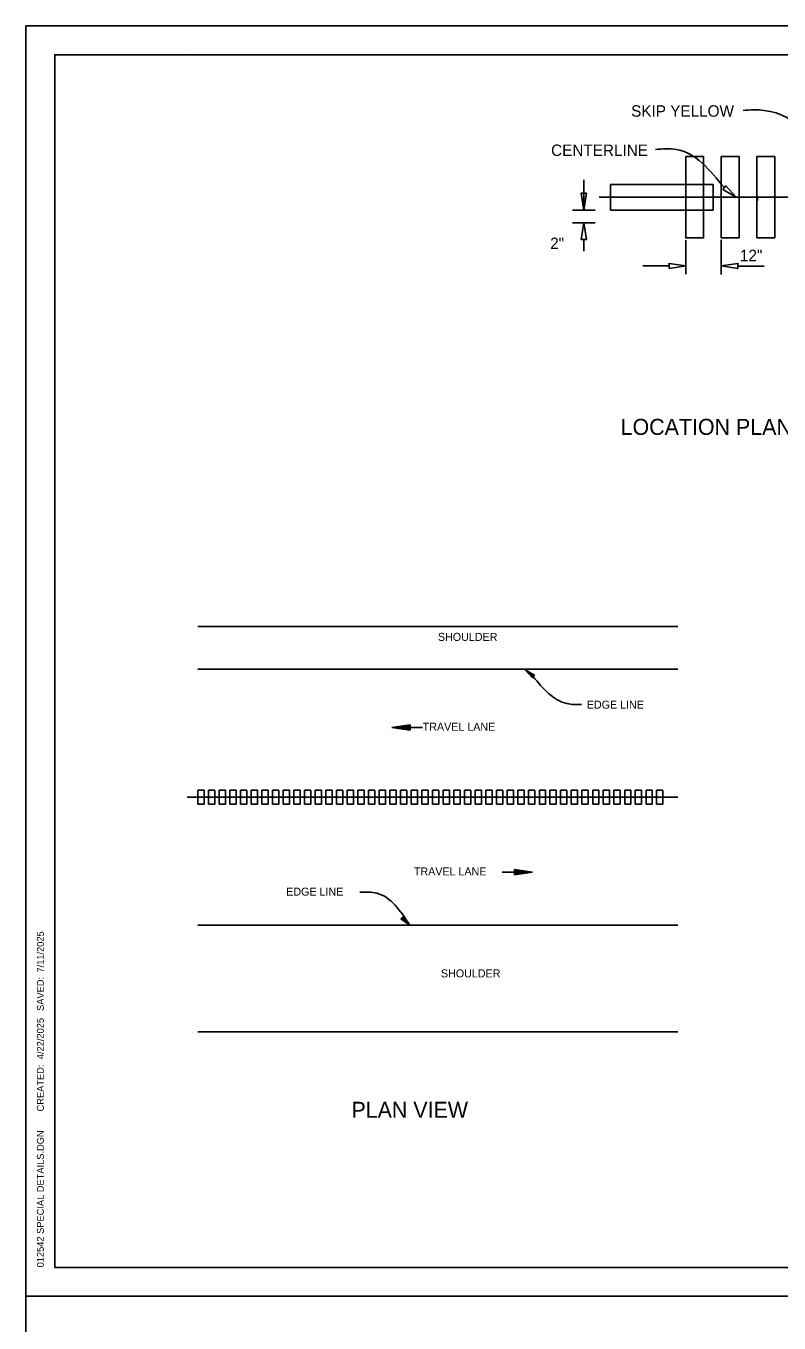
# Model space of a CAD drawing. Extents: x 1371343 to 1373043, y 378740 to 382040.
# Drawn here: x 1371343 to 1371995, y 380917 to 382040 of the extents above; entities that cross this region are included whole.
import ezdxf

# ---------------------------------------------------------------- set-up
doc = ezdxf.new("R2010")
doc.units = 0
for name, color, linetype in [('Default', 7, 'Continuous'), ('E_Existing ROW', 7, 'Continuous'), ('R_Alt Surface Annot', 7, 'Continuous'), ('R_Border Notes', 7, 'Continuous')]:
    doc.layers.add(name, color=color, linetype=linetype)

msp = doc.modelspace()

# ---------------------------------------------------------------- linework, layer by layer
at = {"layer": 'Default'}
for p, q in [((1371826, 381881.1), (1371826, 381907.2)), ((1371839.4, 381892.1), (1372448.3, 381892.1)), ((1371816.2, 381881.1), (1371835.9, 381881.1)), ((1371816.2, 381870.1), (1371835.9, 381870.1)), ((1371826, 381845.4), (1371826, 381855.7)), ((1371914.3, 381825.5), (1371914.3, 381855.1)), ((1371945.1, 381825.4), (1371945.1, 381855.2)), ((1371899.8, 381832.7), (1371877.2, 381832.7)), ((1371982.2, 381832.6), (1371959.5, 381832.6))]:
    msp.add_line(p, q, dxfattribs=at)
for points in [[(1371914.3, 381927.4), (1371914.3, 381856.9), (1371929.7, 381856.9), (1371929.7, 381927.4)], [(1371945.1, 381927.4), (1371945.1, 381856.9), (1371960.5, 381856.9), (1371960.5, 381927.4)], [(1371975.9, 381927.4), (1371975.9, 381856.9), (1371991.4, 381856.9), (1371991.4, 381927.4)]]:
    msp.add_lwpolyline(points, close=True, dxfattribs=at)
for points in [[(1371964, 381967.4), (1371982.2, 381967.4), (1372052.5, 381911.4)], [(1371888.1, 381933.6), (1371906, 381933.6), (1371947.7, 381900.4)]]:
    msp.add_spline(points, degree=3, dxfattribs=at)
at = {"layer": 'E_Existing ROW'}
for p, q in [((1371484, 382019.1), (1371484, 382019.1)), ((1371484, 382019.1), (1371484, 382019.1)), ((1371484, 380919.1), (1371484, 380919.1)), ((1371484, 380919.1), (1371484, 380919.1))]:
    msp.add_line(p, q, dxfattribs=at)
for points in [[(1371342.9, 380940.5), (1373042.9, 380940.5), (1373042.9, 382040.5), (1371342.9, 382040.5)], [(1371367.9, 380965.5), (1373017.9, 380965.5), (1373017.9, 382015.5), (1371367.9, 382015.5)], [(1371342.9, 379840.5), (1373042.9, 379840.5), (1373042.9, 380940.5), (1371342.9, 380940.5)]]:
    msp.add_lwpolyline(points, close=True, dxfattribs=at)
at = {"layer": 'R_Border Notes'}
for p, q in [((1371849, 381903.2), (1371849, 381881.1)), ((1371849, 381903.2), (1371937.9, 381903.2)), ((1371937.9, 381903.2), (1371937.9, 381881.1)), ((1371976.3, 381892.1), (1371976.3, 381889.3)), ((1371849, 381881.1), (1371937.9, 381881.1)), ((1371491.8, 381520.5), (1371907.4, 381520.5)), ((1371491.8, 381483.6), (1371698.6, 381483.6)), ((1371907.4, 381483.6), (1371698.6, 381483.6)), ((1371781.5, 381476), (1371775.1, 381482.9)), ((1371783.2, 381478.2), (1371775.1, 381482.9)), ((1371781.6, 381476.2), (1371776.3, 381481.9)), ((1371783.1, 381478), (1371776.3, 381481.9)), ((1371782.9, 381477.8), (1371777.6, 381480.9)), ((1371781.8, 381476.4), (1371777.6, 381480.9)), ((1371781.9, 381476.6), (1371778.8, 381480)), ((1371782.8, 381477.6), (1371778.8, 381480)), ((1371782.6, 381477.4), (1371780, 381479)), ((1371782.1, 381476.7), (1371780, 381479)), ((1371782.5, 381477.3), (1371781.2, 381478)), ((1371782.2, 381476.9), (1371781.2, 381478)), ((1371781.5, 381476), (1371783.2, 381478.2)), ((1371675.5, 381435.2), (1371659.9, 381432.9)), ((1371686.4, 381432.9), (1371659.9, 381432.9)), ((1371675.5, 381430.6), (1371659.9, 381432.9)), ((1371675.5, 381434.8), (1371662.5, 381432.9)), ((1371675.5, 381431), (1371662.5, 381432.9)), ((1371675.5, 381434.5), (1371665.2, 381432.9)), ((1371675.5, 381431.4), (1371665.2, 381432.9)), ((1371675.5, 381434.1), (1371667.7, 381432.9)), ((1371675.5, 381431.7), (1371667.7, 381432.9)), ((1371675.5, 381433.6), (1371670.4, 381432.9)), ((1371675.5, 381432.1), (1371670.4, 381432.9)), ((1371675.5, 381433.3), (1371673, 381432.9)), ((1371675.5, 381432.5), (1371673, 381432.9)), ((1371675.5, 381435.2), (1371675.5, 381430.6)), ((1371497.2, 381378.8), (1371491.8, 381378.8)), ((1371491.8, 381378.8), (1371491.8, 381366.6)), ((1371497.2, 381378.8), (1371497.2, 381366.6)), ((1371506.4, 381378.8), (1371501, 381378.8)), ((1371501, 381378.8), (1371501, 381366.6)), ((1371506.4, 381378.8), (1371506.4, 381366.6)), ((1371515.7, 381378.8), (1371510.3, 381378.8)), ((1371510.3, 381378.8), (1371510.3, 381366.6)), ((1371515.7, 381378.8), (1371515.7, 381366.6)), ((1371524.9, 381378.8), (1371519.5, 381378.8)), ((1371519.5, 381378.8), (1371519.5, 381366.6)), ((1371524.9, 381378.8), (1371524.9, 381366.6)), ((1371534.1, 381378.8), (1371528.7, 381378.8)), ((1371528.7, 381378.8), (1371528.7, 381366.6)), ((1371534.1, 381378.8), (1371534.1, 381366.6)), ((1371543.4, 381378.8), (1371538, 381378.8)), ((1371538, 381378.8), (1371538, 381366.6)), ((1371543.4, 381378.8), (1371543.4, 381366.6)), ((1371552.6, 381378.8), (1371547.2, 381378.8)), ((1371547.2, 381378.8), (1371547.2, 381366.6)), ((1371552.6, 381378.8), (1371552.6, 381366.6)), ((1371561.9, 381378.8), (1371556.5, 381378.8)), ((1371556.5, 381378.8), (1371556.5, 381366.6)), ((1371561.9, 381378.8), (1371561.9, 381366.6)), ((1371571.1, 381378.8), (1371565.7, 381378.8)), ((1371565.7, 381378.8), (1371565.7, 381366.6)), ((1371571.1, 381378.8), (1371571.1, 381366.6)), ((1371580.3, 381378.8), (1371574.9, 381378.8)), ((1371574.9, 381378.8), (1371574.9, 381366.6)), ((1371580.3, 381378.8), (1371580.3, 381366.6)), ((1371589.6, 381378.8), (1371584.2, 381378.8)), ((1371584.2, 381378.8), (1371584.2, 381366.6)), ((1371589.6, 381378.8), (1371589.6, 381366.6)), ((1371598.8, 381378.8), (1371593.4, 381378.8)), ((1371593.4, 381378.8), (1371593.4, 381366.6)), ((1371598.8, 381378.8), (1371598.8, 381366.6)), ((1371608.1, 381378.8), (1371602.7, 381378.8)), ((1371602.7, 381378.8), (1371602.7, 381366.6)), ((1371608.1, 381378.8), (1371608.1, 381366.6)), ((1371617.3, 381378.8), (1371611.9, 381378.8)), ((1371611.9, 381378.8), (1371611.9, 381366.6)), ((1371617.3, 381378.8), (1371617.3, 381366.6)), ((1371626.5, 381378.8), (1371621.1, 381378.8)), ((1371621.1, 381378.8), (1371621.1, 381366.6)), ((1371626.5, 381378.8), (1371626.5, 381366.6)), ((1371635.8, 381378.8), (1371630.4, 381378.8)), ((1371630.4, 381378.8), (1371630.4, 381366.6)), ((1371635.8, 381378.8), (1371635.8, 381366.6)), ((1371645, 381378.8), (1371639.6, 381378.8)), ((1371639.6, 381378.8), (1371639.6, 381366.6)), ((1371645, 381378.8), (1371645, 381366.6)), ((1371654.3, 381378.8), (1371648.9, 381378.8)), ((1371648.9, 381378.8), (1371648.9, 381366.6)), ((1371654.3, 381378.8), (1371654.3, 381366.6)), ((1371663.5, 381378.8), (1371658.1, 381378.8)), ((1371658.1, 381378.8), (1371658.1, 381366.6)), ((1371663.5, 381378.8), (1371663.5, 381366.6)), ((1371672.7, 381378.8), (1371667.3, 381378.8)), ((1371667.3, 381378.8), (1371667.3, 381366.6)), ((1371672.7, 381378.8), (1371672.7, 381366.6)), ((1371682, 381378.8), (1371676.6, 381378.8)), ((1371676.6, 381378.8), (1371676.6, 381366.6)), ((1371682, 381378.8), (1371682, 381366.6)), ((1371691.2, 381378.8), (1371685.8, 381378.8)), ((1371685.8, 381378.8), (1371685.8, 381366.6)), ((1371691.2, 381378.8), (1371691.2, 381366.6)), ((1371700.5, 381378.8), (1371695.1, 381378.8)), ((1371695.1, 381378.8), (1371695.1, 381366.6)), ((1371700.5, 381378.8), (1371700.5, 381366.6)), ((1371709.7, 381378.8), (1371704.3, 381378.8)), ((1371704.3, 381378.8), (1371704.3, 381366.6)), ((1371709.7, 381378.8), (1371709.7, 381366.6)), ((1371719, 381378.8), (1371713.5, 381378.8)), ((1371713.5, 381378.8), (1371713.5, 381366.6)), ((1371719, 381378.8), (1371719, 381366.6)), ((1371728.2, 381378.8), (1371722.8, 381378.8)), ((1371722.8, 381378.8), (1371722.8, 381366.6)), ((1371728.2, 381378.8), (1371728.2, 381366.6)), ((1371737.4, 381378.8), (1371732, 381378.8)), ((1371732, 381378.8), (1371732, 381366.6)), ((1371737.4, 381378.8), (1371737.4, 381366.6)), ((1371746.7, 381378.8), (1371741.3, 381378.8)), ((1371741.3, 381378.8), (1371741.3, 381366.6)), ((1371746.7, 381378.8), (1371746.7, 381366.6)), ((1371755.9, 381378.8), (1371750.5, 381378.8)), ((1371750.5, 381378.8), (1371750.5, 381366.6)), ((1371755.9, 381378.8), (1371755.9, 381366.6)), ((1371765.2, 381378.8), (1371759.7, 381378.8)), ((1371759.7, 381378.8), (1371759.7, 381366.6)), ((1371765.2, 381378.8), (1371765.2, 381366.6)), ((1371774.4, 381378.8), (1371769, 381378.8)), ((1371769, 381378.8), (1371769, 381366.6)), ((1371774.4, 381378.8), (1371774.4, 381366.6)), ((1371783.6, 381378.8), (1371778.2, 381378.8)), ((1371778.2, 381378.8), (1371778.2, 381366.6)), ((1371783.6, 381378.8), (1371783.6, 381366.6)), ((1371792.9, 381378.8), (1371787.5, 381378.8)), ((1371787.5, 381378.8), (1371787.5, 381366.6)), ((1371792.9, 381378.8), (1371792.9, 381366.6)), ((1371802.1, 381378.8), (1371796.7, 381378.8)), ((1371796.7, 381378.8), (1371796.7, 381366.6)), ((1371802.1, 381378.8), (1371802.1, 381366.6)), ((1371811.4, 381378.8), (1371805.9, 381378.8)), ((1371805.9, 381378.8), (1371805.9, 381366.6)), ((1371811.4, 381378.8), (1371811.4, 381366.6)), ((1371820.6, 381378.8), (1371815.2, 381378.8)), ((1371815.2, 381378.8), (1371815.2, 381366.6)), ((1371820.6, 381378.8), (1371820.6, 381366.6)), ((1371829.8, 381378.8), (1371824.4, 381378.8)), ((1371824.4, 381378.8), (1371824.4, 381366.6)), ((1371829.8, 381378.8), (1371829.8, 381366.6)), ((1371839.1, 381378.8), (1371833.7, 381378.8)), ((1371833.7, 381378.8), (1371833.7, 381366.6)), ((1371839.1, 381378.8), (1371839.1, 381366.6)), ((1371848.3, 381378.8), (1371842.9, 381378.8)), ((1371842.9, 381378.8), (1371842.9, 381366.6)), ((1371848.3, 381378.8), (1371848.3, 381366.6)), ((1371857.6, 381378.8), (1371852.1, 381378.8)), ((1371852.1, 381378.8), (1371852.1, 381366.6)), ((1371857.6, 381378.8), (1371857.6, 381366.6)), ((1371866.8, 381378.8), (1371861.4, 381378.8)), ((1371861.4, 381378.8), (1371861.4, 381366.6)), ((1371866.8, 381378.8), (1371866.8, 381366.6)), ((1371876, 381378.8), (1371870.6, 381378.8)), ((1371870.6, 381378.8), (1371870.6, 381366.6)), ((1371876, 381378.8), (1371876, 381366.6)), ((1371885.3, 381378.8), (1371879.9, 381378.8)), ((1371879.9, 381378.8), (1371879.9, 381366.6)), ((1371885.3, 381378.8), (1371885.3, 381366.6)), ((1371894.5, 381378.8), (1371889.1, 381378.8)), ((1371889.1, 381378.8), (1371889.1, 381366.6)), ((1371894.5, 381378.8), (1371894.5, 381366.6)), ((1371482.6, 381372.7), (1371907.4, 381372.7)), ((1371491.8, 381366.6), (1371497.2, 381366.6)), ((1371501, 381366.6), (1371506.4, 381366.6)), ((1371510.3, 381366.6), (1371515.7, 381366.6)), ((1371519.5, 381366.6), (1371524.9, 381366.6)), ((1371528.7, 381366.6), (1371534.1, 381366.6)), ((1371538, 381366.6), (1371543.4, 381366.6)), ((1371547.2, 381366.6), (1371552.6, 381366.6)), ((1371556.5, 381366.6), (1371561.9, 381366.6)), ((1371565.7, 381366.6), (1371571.1, 381366.6)), ((1371574.9, 381366.6), (1371580.3, 381366.6)), ((1371584.2, 381366.6), (1371589.6, 381366.6)), ((1371593.4, 381366.6), (1371598.8, 381366.6)), ((1371602.7, 381366.6), (1371608.1, 381366.6)), ((1371611.9, 381366.6), (1371617.3, 381366.6)), ((1371621.1, 381366.6), (1371626.5, 381366.6)), ((1371630.4, 381366.6), (1371635.8, 381366.6)), ((1371639.6, 381366.6), (1371645, 381366.6)), ((1371648.9, 381366.6), (1371654.3, 381366.6)), ((1371658.1, 381366.6), (1371663.5, 381366.6)), ((1371667.3, 381366.6), (1371672.7, 381366.6)), ((1371676.6, 381366.6), (1371682, 381366.6)), ((1371685.8, 381366.6), (1371691.2, 381366.6)), ((1371695.1, 381366.6), (1371700.5, 381366.6)), ((1371704.3, 381366.6), (1371709.7, 381366.6)), ((1371713.5, 381366.6), (1371719, 381366.6)), ((1371722.8, 381366.6), (1371728.2, 381366.6)), ((1371732, 381366.6), (1371737.4, 381366.6)), ((1371741.3, 381366.6), (1371746.7, 381366.6)), ((1371750.5, 381366.6), (1371755.9, 381366.6)), ((1371759.7, 381366.6), (1371765.2, 381366.6)), ((1371769, 381366.6), (1371774.4, 381366.6)), ((1371778.2, 381366.6), (1371783.6, 381366.6)), ((1371787.5, 381366.6), (1371792.9, 381366.6)), ((1371796.7, 381366.6), (1371802.1, 381366.6)), ((1371805.9, 381366.6), (1371811.4, 381366.6)), ((1371815.2, 381366.6), (1371820.6, 381366.6)), ((1371824.4, 381366.6), (1371829.8, 381366.6)), ((1371833.7, 381366.6), (1371839.1, 381366.6)), ((1371842.9, 381366.6), (1371848.3, 381366.6)), ((1371852.1, 381366.6), (1371857.6, 381366.6)), ((1371861.4, 381366.6), (1371866.8, 381366.6)), ((1371870.6, 381366.6), (1371876, 381366.6)), ((1371879.9, 381366.6), (1371885.3, 381366.6)), ((1371889.1, 381366.6), (1371894.5, 381366.6)), ((1371755.2, 381307.8), (1371781.6, 381307.8)), ((1371766.1, 381310.1), (1371781.6, 381307.8)), ((1371766.1, 381305.5), (1371766.1, 381310.1)), ((1371766.1, 381309.7), (1371779, 381307.8)), ((1371766.1, 381309.3), (1371776.4, 381307.8)), ((1371766.1, 381308.9), (1371773.8, 381307.8)), ((1371766.1, 381308.6), (1371771.1, 381307.8)), ((1371766.1, 381308.2), (1371768.5, 381307.8)), ((1371766.1, 381305.5), (1371781.6, 381307.8)), ((1371766.1, 381307.1), (1371771.1, 381307.8)), ((1371766.1, 381306.2), (1371776.4, 381307.8)), ((1371766.1, 381305.8), (1371779, 381307.8)), ((1371766.1, 381306.6), (1371773.8, 381307.8)), ((1371766.1, 381307.4), (1371768.5, 381307.8)), ((1371669.7, 381269.3), (1371667.7, 381267.3)), ((1371667.7, 381267.3), (1371675.3, 381261.9)), ((1371667.9, 381267.5), (1371674.2, 381263)), ((1371668.1, 381267.7), (1371673.1, 381264.1)), ((1371668.2, 381267.8), (1371672, 381265.1)), ((1371668.4, 381268), (1371670.9, 381266.2)), ((1371668.5, 381268.2), (1371669.7, 381267.3)), ((1371668.8, 381268.5), (1371669.7, 381267.3)), ((1371669, 381268.6), (1371670.9, 381266.2)), ((1371669.2, 381268.8), (1371672, 381265.1)), ((1371669.3, 381269), (1371673.1, 381264.1)), ((1371669.5, 381269.1), (1371674.2, 381263)), ((1371669.7, 381269.3), (1371675.3, 381261.9)), ((1371491.8, 381261.8), (1371698.6, 381261.8)), ((1371907.4, 381261.8), (1371698.6, 381261.8)), ((1371805.9, 381261.8), (1371907.4, 381261.8)), ((1371491.8, 381169.4), (1371907.4, 381169.4))]:
    msp.add_line(p, q, dxfattribs=at)
for points in [[(1371823.8, 381895.6), (1371828.2, 381895.6), (1371826, 381881.1)], [(1371946.4, 381898.8), (1371948.9, 381902), (1371958, 381892.1)], [(1371823.8, 381855.7), (1371828.2, 381855.7), (1371826, 381870.1)], [(1371899.8, 381830.5), (1371899.8, 381834.9), (1371914.3, 381832.7)], [(1371959.5, 381830.5), (1371959.5, 381834.8), (1371945.1, 381832.7)]]:
    msp.add_lwpolyline(points, close=True, dxfattribs=at)
for points in [[(1371824, 381452.8), (1371811.4, 381453.7), (1371782, 381477.2)], [(1371632.1, 381290.5), (1371646.9, 381289.5), (1371675.3, 381261.9)]]:
    msp.add_spline(points, degree=3, dxfattribs=at)

# ---------------------------------------------------------------- texts
at = {"layer": 'Default'}
for s, p in [('SKIP YELLOW', (1371867, 381961.9)), ('CENTERLINE', (1371797.7, 381927.9)), ('2"', (1371796.9, 381847.3)), ('12"', (1371961.2, 381836.8))]:
    msp.add_text(s, height=9.9, dxfattribs=at).set_placement(p)
at = {"layer": 'R_Alt Surface Annot'}
for s, p in [('7/11/2025', (1371358.4, 381220.8)), ('  SAVED: ', (1371358.4, 381183.1)), ('4/22/2025', (1371358.4, 381145.8)), ('     CREATED: ', (1371358.4, 381089.4)), ('012542 SPECIAL DETAILS.DGN', (1371358.4, 380965.5))]:
    msp.add_text(s, height=6, rotation=90, dxfattribs=at).set_placement(p)
at = {"layer": 'R_Border Notes'}
for s, height, p in [('LOCATION PLAN OF CENTERLINE RUMBLE STRIPES', 13.86, (1371857.9, 381686.4)), ('SHOULDER', 6.93, (1371699.7, 381508)), ('EDGE LINE', 6.93, (1371828.6, 381449.3)), ('TRAVEL LANE', 6.93, (1371686.5, 381430.2)), ('TRAVEL LANE', 6.93, (1371678.9, 381304.9)), ('EDGE LINE', 6.93, (1371568.3, 381287.4)), ('SHOULDER', 6.93, (1371702.3, 381216.6)), ('PLAN VIEW ', 13.86, (1371624.8, 381095))]:
    msp.add_text(s, height=height, dxfattribs=at).set_placement(p)

doc.saveas('drawing.dxf')
